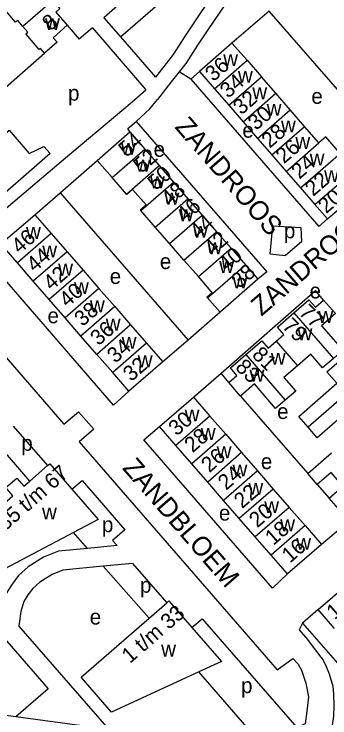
# Model space of a CAD drawing. Extents: x 155854 to 157362, y 383621 to 384685.
# Drawn here: x 156294.2 to 156376.4, y 383977 to 384160.1 of the extents above; entities that cross this region are included whole.
import ezdxf

# ---------------------------------------------------------------- set-up
doc = ezdxf.new("R2010")
doc.units = 0
for name, color, linetype in [('BLT_Basislijn', 7, 'Continuous'), ('BLT_Bebouwing', 7, 'Continuous'), ('BLT_Centroide', 7, 'Continuous'), ('BLT_Huisnummer', 7, 'Continuous'), ('BLT_Huisnummer_ tussenligend', 7, 'Continuous'), ('BLT_Huisnummer_reeks', 7, 'Continuous'), ('BLT_Onderverdeling_panden', 7, 'Continuous'), ('BLT_Straatnaam', 7, 'Continuous')]:
    doc.layers.add(name, color=color, linetype=linetype)

msp = doc.modelspace()

# ---------------------------------------------------------------- linework, layer by layer
at = {"layer": 'BLT_Basislijn'}
for p, q in [((156321.19, 384162.34), (156317.57, 384159.18)), ((156360.59, 384160.92), (156350.9, 384152.57)), ((156393.89, 384122.59), (156360.59, 384160.92)), ((156317.57, 384159.18), (156321.9, 384154.19)), ((156308.04, 384157.22), (156311.17, 384153.6)), ((156314.56, 384156.55), (156311.17, 384153.6)), ((156314.56, 384156.55), (156328.5, 384140.46)), ((156321.9, 384154.19), (156330.99, 384143.7)), ((156288.38, 384137.89), (156302.08, 384149.93)), ((156340.22, 384143.23), (156337.17, 384145.09)), ((156342.43, 384145.17), (156340.22, 384143.23)), ((156324.94, 384137.33), (156328.5, 384140.46)), ((156307.03, 384122.29), (156324.94, 384137.33)), ((156283.29, 384102.22), (156307.03, 384122.29)), ((156306.17, 384113.65), (156315.79, 384122.07)), ((156299.59, 384107.93), (156306.17, 384113.65)), ((156306.17, 384113.65), (156339.48, 384075.31)), ((156361.41, 384105), (156360.74, 384097.79)), ((156361.41, 384105), (156368.87, 384104.57)), ((156368.87, 384104.57), (156368.97, 384100.91)), ((156368.97, 384100.91), (156364.85, 384097.34)), ((156360.74, 384097.79), (156364.85, 384097.34)), ((156348.09, 384066.73), (156372.63, 384088.2)), ((156374.77, 384085.74), (156372.63, 384088.2)), ((156347.79, 384082.6), (156339.48, 384075.31)), ((156339.48, 384075.31), (156332.88, 384069.66)), ((156340.86, 384060.49), (156348.09, 384066.73)), ((156350.05, 384064.27), (156348.09, 384066.73)), ((156353.09, 384060.75), (156370.62, 384040.61)), ((156293.99, 384052.96), (156302.93, 384042.66)), ((156327.92, 384049.36), (156332.03, 384052.82)), ((156298.33, 384038.66), (156286.48, 384052.28)), ((156361.43, 384010.78), (156327.92, 384049.36)), ((156373.11, 384037.76), (156376.19, 384034.21)), ((156381.34, 384028.23), (156374.19, 384022.15)), ((156313.3, 384021.14), (156309.63, 384025.29)), ((156320.98, 384021.87), (156313.3, 384021.14)), ((156325, 384017.23), (156317.39, 384016.51)), ((156329.34, 384002.97), (156317.39, 384016.51)), ((156325, 384017.23), (156333.92, 384006.95)), ((156365.34, 384014.49), (156361.43, 384010.78)), ((156373.34, 384005.22), (156369.3, 384001.72)), ((156369.3, 384001.72), (156403.93, 383961.86)), ((156318.94, 383974.05), (156295.43, 384001)), ((156360.11, 383968.58), (156342.24, 383989.01)), ((156318.94, 383974.05), (156294.62, 383977.28))]:
    msp.add_line(p, q, dxfattribs=at)
for points in [[(156369.54, 384185.64), (156365.42, 384181.74), (156361.35, 384177.55), (156357.13, 384172.67), (156353.12, 384167.99), (156350.17, 384164.27), (156346.4, 384158.74), (156341.94, 384152.03), (156338.87, 384147.26), (156337.17, 384145.09)], [(156351.31, 384172.03), (156346.94, 384166.64), (156343.09, 384160.97), (156338.59, 384154.22), (156335.61, 384149.58), (156330.99, 384143.7)], [(156321.9, 384154.19), (156332.95, 384163.76), (156328.6, 384168.79)], [(156337.17, 384145.09), (156335.12, 384142.48), (156331.53, 384137.89)], [(156340.22, 384143.23), (156373.54, 384104.88), (156375.73, 384106.85)], [(156325.95, 384132.21), (156329.53, 384135.44), (156331.53, 384137.89)], [(156324.33, 384129.49), (156323.82, 384130.4), (156325.95, 384132.21)], [(156325.95, 384132.21), (156359.95, 384093.08), (156357.61, 384091.13)], [(156324.05, 384062.01), (156320.05, 384058.42), (156286.74, 384096.77)], [(156276.92, 384088.24), (156307.18, 384053.41), (156310.96, 384056.69), (156314.93, 384052.11), (156311.16, 384048.83), (156362.68, 383989.52), (156366.72, 383992.5), (156368.14, 383991.05), (156369.04, 383989.47), (156370.17, 383986.09), (156370.85, 383982.49), (156370.38, 383978.82), (156369.95, 383975.5), (156367.77, 383974.52)], [(156309.25, 384036.53), (156311.91, 384038.78), (156323.02, 384025.98), (156319.84, 384023.18), (156320.98, 384021.87)], [(156313.3, 384021.14), (156305.72, 384020.42), (156301.83, 384018.84), (156297.89, 384016.37), (156295.36, 384014.11), (156293.66, 384011.87), (156292.16, 384009.4), (156291.12, 384005.94)], [(156317.39, 384016.51), (156306.92, 384015.51), (156304.11, 384014.37), (156300.9, 384012.36), (156299.05, 384010.7), (156297.8, 384009.05), (156296.77, 384007.35), (156295.97, 384004.69), (156295.43, 384001)], [(156276.3, 384015.32), (156303.06, 383984.64), (156294.62, 383977.28)], [(156340.49, 384000.58), (156343.13, 384002.83), (156367.77, 383974.51)], [(156369.3, 384001.72), (156368.39, 383999.97), (156370.56, 383997.41), (156372.6, 383994.73), (156374.65, 383992.04), (156375.41, 383990.38), (156376.18, 383988.47), (156377.2, 383985.27), (156377.33, 383983.1), (156377.46, 383980.29), (156377.33, 383977.47), (156376.69, 383973.38), (156375.92, 383967.54), (156378.01, 383961.92)], [(156294.62, 383977.28), (156234.37, 383985.27)]]:
    msp.add_lwpolyline(points, dxfattribs=at)
at = {"layer": 'BLT_Bebouwing'}
for p, q in [((156350.9, 384152.57), (156342.43, 384145.17)), ((156354.86, 384148.13), (156358.59, 384143.83)), ((156342.43, 384145.17), (156346.32, 384140.69)), ((156362.32, 384139.52), (156358.59, 384143.83)), ((156346.32, 384140.69), (156350.06, 384136.39)), ((156366.06, 384135.22), (156362.32, 384139.52)), ((156350.06, 384136.39), (156353.8, 384132.09)), ((156369.79, 384130.92), (156366.06, 384135.22)), ((156353.8, 384132.09), (156357.53, 384127.79)), ((156315.79, 384122.07), (156324.33, 384129.49)), ((156324.33, 384129.49), (156328.23, 384125)), ((156373.52, 384126.61), (156369.79, 384130.92)), ((156357.53, 384127.79), (156361.27, 384123.49)), ((156328.23, 384125), (156331.98, 384120.7)), ((156319.7, 384117.58), (156315.79, 384122.07)), ((156361.27, 384123.49), (156365.01, 384119.19)), ((156331.98, 384120.7), (156335.71, 384116.4)), ((156365.01, 384119.19), (156368.74, 384114.89)), ((156323.44, 384113.29), (156319.7, 384117.58)), ((156335.71, 384116.4), (156339.45, 384112.1)), ((156368.74, 384114.89), (156372.48, 384110.59)), ((156375.73, 384106.85), (156385.54, 384115.35)), ((156323.52, 384113.2), (156323.44, 384113.29)), ((156339.45, 384112.1), (156343.18, 384107.8)), ((156372.48, 384110.59), (156375.73, 384106.85)), ((156290.76, 384100.33), (156299.59, 384107.93)), ((156299.59, 384107.93), (156303.87, 384103.04)), ((156343.18, 384107.8), (156346.92, 384103.5)), ((156334.67, 384100.41), (156330.93, 384104.7)), ((156303.87, 384103.04), (156308.01, 384098.29)), ((156346.92, 384103.5), (156350.66, 384099.2)), ((156295.06, 384095.39), (156290.76, 384100.33)), ((156338.41, 384096.11), (156334.67, 384100.41)), ((156308.01, 384098.29), (156312.14, 384093.53)), ((156350.66, 384099.2), (156354.39, 384094.9)), ((156299.19, 384090.63), (156295.06, 384095.39)), ((156342.16, 384091.82), (156338.41, 384096.11)), ((156354.39, 384094.9), (156357.61, 384091.13)), ((156312.14, 384093.53), (156316.27, 384088.78)), ((156345.52, 384087.96), (156342.16, 384091.82)), ((156357.61, 384091.13), (156347.79, 384082.6)), ((156303.32, 384085.87), (156299.19, 384090.63)), ((156316.27, 384088.78), (156320.4, 384084.02)), ((156307.45, 384081.12), (156303.32, 384085.87)), ((156374.77, 384085.74), (156377.85, 384082.2)), ((156320.4, 384084.02), (156324.53, 384079.27)), ((156311.59, 384076.36), (156307.45, 384081.12)), ((156324.53, 384079.27), (156328.67, 384074.51)), ((156315.72, 384071.61), (156311.59, 384076.36)), ((156328.67, 384074.51), (156332.88, 384069.66)), ((156319.85, 384066.85), (156315.72, 384071.61)), ((156332.88, 384069.66), (156324.05, 384062.01)), ((156324.05, 384062.01), (156319.85, 384066.85)), ((156353.09, 384060.75), (156350.05, 384064.27)), ((156332.03, 384052.82), (156340.86, 384060.49)), ((156340.86, 384060.49), (156345.15, 384055.56)), ((156345.15, 384055.56), (156349.27, 384050.81)), ((156370.7, 384052.68), (156368.27, 384055.48)), ((156336.32, 384047.88), (156332.03, 384052.82)), ((156349.27, 384050.81), (156353.4, 384046.06)), ((156340.45, 384043.13), (156336.32, 384047.88)), ((156353.4, 384046.06), (156357.53, 384041.31)), ((156370.62, 384040.61), (156376.81, 384046)), ((156344.58, 384038.38), (156340.45, 384043.13)), ((156357.53, 384041.31), (156361.66, 384036.56)), ((156373.11, 384037.76), (156370.62, 384040.61)), ((156348.7, 384033.63), (156344.58, 384038.38)), ((156361.66, 384036.56), (156365.79, 384031.81)), ((156379.24, 384030.7), (156376.19, 384034.21)), ((156352.82, 384028.89), (156348.7, 384033.63)), ((156365.79, 384031.81), (156369.92, 384027.05)), ((156356.96, 384024.13), (156352.82, 384028.89)), ((156369.92, 384027.05), (156374.19, 384022.15)), ((156361.09, 384019.38), (156356.96, 384024.13)), ((156374.19, 384022.15), (156365.34, 384014.49)), ((156365.34, 384014.49), (156361.09, 384019.38)), ((156373.34, 384005.22), (156382.16, 384012.89)), ((156377.6, 384000.32), (156373.34, 384005.22))]:
    msp.add_line(p, q, dxfattribs=at)
for points in [[(156296.46, 384156.93), (156295.13, 384158.46), (156294.6, 384158), (156291.06, 384162.08), (156298.34, 384168.39)], [(156304.26, 384163.66), (156306.1, 384161.54), (156305.07, 384160.64), (156308.04, 384157.22)], [(156297.22, 384154.98), (156297.75, 384155.44), (156296.46, 384156.93)], [(156308.04, 384157.22), (156304.38, 384153.99), (156305.39, 384152.81), (156302.08, 384149.93)], [(156302.08, 384149.93), (156301.03, 384151.13), (156300.76, 384150.9), (156297.22, 384154.98)], [(156354.86, 384148.13), (156350.9, 384152.57)], [(156286.19, 384108.79), (156278.6, 384117.47), (156292.87, 384129.91), (156298.15, 384123.82), (156301.96, 384125.68), (156303.55, 384123.89), (156286.19, 384108.79)], [(156377.26, 384122.31), (156379.06, 384123.88), (156375.31, 384128.17), (156373.52, 384126.61)], [(156328.54, 384110.49), (156325.02, 384114.52), (156323.52, 384113.2)], [(156327.19, 384108.99), (156327.03, 384109.17), (156328.54, 384110.49)], [(156330.93, 384104.7), (156327.19, 384108.99)], [(156344.53, 384086.34), (156344.39, 384086.5), (156345.76, 384087.69), (156345.52, 384087.96)], [(156347.79, 384082.6), (156344.53, 384086.34)], [(156367.01, 384082.4), (156370.91, 384085.79), (156372.61, 384083.86), (156374.77, 384085.74)], [(156362.45, 384075.03), (156364.44, 384076.75), (156362.76, 384078.7), (156367.01, 384082.4)], [(156377.85, 384082.2), (156374.22, 384079.05), (156379.74, 384072.68), (156377.29, 384070.55)], [(156354.52, 384071.53), (156358.69, 384075.15), (156360.36, 384073.21), (156362.45, 384075.03)], [(156350.05, 384064.27), (156352.21, 384066.14), (156350.54, 384068.07), (156354.52, 384071.53)], [(156377.29, 384070.55), (156374.5, 384068.14), (156371.44, 384071.66), (156367.96, 384068.65)], [(156368.27, 384055.48), (156378.21, 384064.09), (156375.63, 384067.07), (156380.72, 384071.48), (156383.29, 384068.5), (156387.01, 384071.73)], [(156367.96, 384068.65), (156364.44, 384065.59), (156367.49, 384062.07), (156364.78, 384059.72)], [(156391.83, 384066.18), (156388.11, 384062.96), (156390.69, 384059.99), (156385.61, 384055.57), (156383.02, 384058.55), (156373.09, 384049.92), (156370.7, 384052.68)], [(156364.78, 384059.72), (156362.25, 384057.53), (156356.73, 384063.9), (156353.09, 384060.75)], [(156298.33, 384038.66), (156302.93, 384042.66)], [(156302.93, 384042.66), (156303.52, 384043.13), (156309.25, 384036.53)], [(156376.19, 384034.21), (156379.8, 384037.35), (156376.72, 384040.9), (156373.11, 384037.76)], [(156280.73, 384023.33), (156293.89, 384034.82), (156292.04, 384036.95), (156294.89, 384039.42), (156296.74, 384037.3), (156298.33, 384038.66)], [(156309.25, 384036.53), (156316.08, 384028.68)], [(156316.08, 384028.68), (156309.63, 384025.29)], [(156309.63, 384025.29), (156288.58, 384014.2), (156280.73, 384023.33)], [(156329.34, 384002.97), (156333.92, 384006.95)], [(156333.92, 384006.95), (156334.51, 384007.46), (156340.49, 384000.58)], [(156311.67, 383987.62), (156329.34, 384002.97)], [(156340.49, 384000.58), (156348.16, 383991.75), (156342.24, 383989.01)], [(156342.24, 383989.01), (156319.57, 383978.53), (156311.67, 383987.62)]]:
    msp.add_lwpolyline(points, dxfattribs=at)
at = {"layer": 'BLT_Onderverdeling_panden'}
for p, q in [((156304.26, 384163.66), (156296.46, 384156.93)), ((156346.32, 384140.69), (156354.86, 384148.13)), ((156350.06, 384136.39), (156358.59, 384143.83)), ((156353.8, 384132.09), (156362.32, 384139.52)), ((156357.53, 384127.79), (156366.06, 384135.22)), ((156361.27, 384123.49), (156369.79, 384130.92)), ((156365.01, 384119.19), (156373.52, 384126.61)), ((156319.7, 384117.58), (156328.23, 384125)), ((156368.74, 384114.89), (156377.26, 384122.31)), ((156323.44, 384113.29), (156331.98, 384120.7)), ((156372.48, 384110.59), (156382.27, 384119.12)), ((156327.19, 384108.99), (156335.71, 384116.4)), ((156330.93, 384104.7), (156339.45, 384112.1)), ((156334.67, 384100.41), (156343.18, 384107.8)), ((156303.87, 384103.04), (156295.06, 384095.39)), ((156338.41, 384096.11), (156346.92, 384103.5)), ((156308.01, 384098.29), (156299.19, 384090.63)), ((156342.16, 384091.82), (156350.66, 384099.2)), ((156344.53, 384086.34), (156354.39, 384094.9)), ((156312.14, 384093.53), (156303.32, 384085.87)), ((156316.27, 384088.78), (156307.45, 384081.12)), ((156320.4, 384084.02), (156311.59, 384076.36)), ((156367.01, 384082.4), (156377.29, 384070.55)), ((156324.53, 384079.27), (156315.72, 384071.61)), ((156328.67, 384074.51), (156319.85, 384066.85)), ((156362.45, 384075.03), (156367.96, 384068.65)), ((156354.52, 384071.53), (156364.78, 384059.72)), ((156389.43, 384068.95), (156370.7, 384052.68)), ((156345.15, 384055.56), (156336.32, 384047.88)), ((156349.27, 384050.81), (156340.45, 384043.13)), ((156353.4, 384046.06), (156344.58, 384038.38)), ((156357.53, 384041.31), (156348.7, 384033.63)), ((156361.66, 384036.56), (156352.82, 384028.89)), ((156365.79, 384031.81), (156356.96, 384024.13)), ((156369.92, 384027.05), (156361.09, 384019.38))]:
    msp.add_line(p, q, dxfattribs=at)

# ---------------------------------------------------------------- texts
at = {"layer": 'BLT_Centroide'}
for s, p in [('w', (156302.25, 384155.98)), ('w', (156348.62, 384146.62)), ('w', (156352.46, 384142.25)), ('p', (156308.23, 384137.6)), ('w', (156356.2, 384137.97)), ('e', (156371.57, 384136.78)), ('w', (156359.93, 384133.66)), ('e', (156353.61, 384127.97)), ('w', (156363.66, 384129.34)), ('w', (156367.4, 384125.06)), ('w', (156322.02, 384123.53)), ('e', (156330.5, 384123)), ('w', (156371.13, 384120.75)), ('w', (156325.84, 384119.16)), ('w', (156374.87, 384116.44)), ('w', (156329.58, 384114.84)), ('w', (156333.32, 384110.56)), ('w', (156337.06, 384106.25)), ('w', (156297.3, 384101.66)), ('w', (156340.8, 384101.97)), ('p', (156364.43, 384101.8)), ('w', (156344.54, 384097.66)), ('w', (156301.53, 384096.84)), ('e', (156332.13, 384093.8)), ('w', (156305.66, 384092.09)), ('w', (156347.59, 384092.78)), ('e', (156319.09, 384089.92)), ('w', (156351.09, 384088.75)), ('w', (156309.79, 384087.31)), ('e', (156371.11, 384086.15)), ('w', (156313.93, 384082.56)), ('e', (156302.89, 384079.7)), ('w', (156373.38, 384079.8)), ('w', (156318.05, 384077.81)), ('w', (156367.97, 384075.28)), ('w', (156322.2, 384073.06)), ('w', (156326.37, 384068.25)), ('w', (156361.02, 384068.92)), ('w', (156355.48, 384064.53)), ('e', (156362.66, 384054.79)), ('w', (156338.59, 384054.19)), ('w', (156342.79, 384049.34)), ('p', (156296.07, 384046.52)), ('w', (156346.92, 384044.59)), ('e', (156358.43, 384041.76)), ('w', (156351.05, 384039.84)), ('w', (156355.18, 384035.09)), ('w', (156359.3, 384030.34)), ('w', (156301.46, 384028.66)), ('e', (156347.52, 384028.37)), ('w', (156363.45, 384025.59)), ('p', (156317.06, 384025.35)), ('w', (156367.64, 384020.78)), ('p', (156326.96, 384009.6)), ('e', (156313.88, 384001.33)), ('w', (156332.47, 383993)), ('p', (156353.28, 383983.49))]:
    msp.add_text(s, height=4, dxfattribs=at).set_placement(p)
at = {"layer": 'BLT_Huisnummer'}
for s, rotation, p in [('8', 41.1881, (156303.67, 384155.58)), ('36', 40.9828, (156346.06, 384142.38)), ('32', 40.9828, (156353.34, 384133.73)), ('54', 40.9828, (156323.49, 384122.74)), ('26', 40.9828, (156364.46, 384121.04)), ('50', 40.9828, (156331.07, 384114.09)), ('20', 40.9828, (156375.43, 384108.05)), ('44', 40.9828, (156342.04, 384101.4)), ('46', 40.9824, (156295.64, 384097.58)), ('38', 40.9828, (156352.87, 384088.57)), ('40', 40.9824, (156308.06, 384083.66)), ('38', 40.9824, (156312.01, 384078.68)), ('77', 315.9095, (156368.08, 384082.2)), ('32', 40.9824, (156324.68, 384064.35)), ('83', 315.9095, (156351.54, 384067.98)), ('30', 40.9824, (156336.51, 384050.21)), ('24', 40.9824, (156349.39, 384036.09)), ('22', 40.9824, (156353.55, 384031.32)), ('16', 40.9824, (156366.01, 384017.16)), ('14', 40.9824, (156377.64, 384002.41))]:
    msp.add_text(s, height=4, rotation=rotation, dxfattribs=at).set_placement(p)
at = {"layer": 'BLT_Huisnummer_ tussenligend'}
for s, rotation, p in [('34', 40.9828, (156349.92, 384138.05)), ('30', 40.9828, (156357.19, 384129.7)), ('28', 40.9828, (156360.75, 384125.07)), ('52', 40.9828, (156327.37, 384118.58)), ('24', 40.9828, (156368.47, 384117.02)), ('22', 40.9828, (156372.04, 384112.54)), ('48', 40.9828, (156334.63, 384109.91)), ('46', 40.9828, (156338.64, 384105.73)), ('42', 40.9828, (156345.76, 384097.08)), ('44', 40.9824, (156299.55, 384092.8)), ('40', 40.9828, (156349.46, 384092.9)), ('42', 40.9824, (156303.92, 384088.03)), ('36', 40.9824, (156316.16, 384073.69)), ('79', 315.9095, (156363.73, 384078.64)), ('34', 40.9824, (156320.52, 384069.12)), ('81', 315.9095, (156355.88, 384071.2)), ('28', 40.9824, (156340.67, 384045.86)), ('26', 40.9824, (156345.03, 384040.66)), ('20', 40.9824, (156357.49, 384026.32)), ('18', 40.9824, (156361.66, 384021.74))]:
    msp.add_text(s, height=4, rotation=rotation, dxfattribs=at).set_placement(p)
at = {"layer": 'BLT_Huisnummer_reeks'}
for s, rotation, p in [('35 t/m 67', 40.9822, (156291.88, 384025.53)), ('1 t/m 33', 40.9825, (156324.36, 383991.05))]:
    msp.add_text(s, height=4, rotation=rotation, dxfattribs=at).set_placement(p)
at = {"layer": 'BLT_Straatnaam'}
for s, rotation, p in [('ZANDROOS', 310.9822, (156335.83, 384130.66)), ('ZANDROOS', 40.9822, (156358.59, 384081.38)), ('ZANDBLOEM', 310.9822, (156322.18, 384041.94))]:
    msp.add_text(s, height=5, rotation=rotation, dxfattribs=at).set_placement(p)

doc.saveas('drawing.dxf')
